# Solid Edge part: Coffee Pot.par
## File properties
Document Number: DOC NUMBER
Revision: REV NUMBER
Project Name: COFFEE MAKER
Title: COFFEE POT
Subject: COFFEE MAKER
Author: rkriggs
Keywords: POT
Comments: COMMENTS FIELD
Template: Normal.par
Last saved by: plm
Revision: 53
Application: Solid Edge
Category: COFFEE MAKER
Manager: MANAGER FIELD
Company: UGS
CUSTOM NAME FIELD: CUSTOM VALUE FIELD
Density: 0.09375032274 lbm/in^3
Accuracy: 0.99
圖檔名稱: Coffee Pot.par
圖檔編號: Coffee Pot.par
major_rev: A
classification: Mechanical/Part
generation: 2
id: 6B58A722315E453AA4D6A4DDAE715D26
authoring_tool: Solid Edge
thumbnail: vault:///?fileId=0F645047CE554D2D99C893C972FE50EA
Material: Glass, general industrial
Face Style: White (glass)
Fill Style: ANSI36(Marble)
Virtual Style: White (Glass)
Coef. of Thermal Exp: 0.0
Thermal Conductivity: 0.0
Specific Heat: 0.0
Modulus of Elasticity: 0.0
Poisson's Ratio: 0.0
Yield Stress: 0.0
Ultimate Stress: 0.0
Elongation: 0.0
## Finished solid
Body 1: solid body, 84 faces, 162 edges, 80 vertices.
  Faces by surface: blend 19, torus 18, spline 17, cylinder 12, plane 11, cone 7
  Edges by curve: circle 58, intersection 47, curve on surface 35, line 14, ellipse 8
Bounding box of the edges (mm; curved faces can reach further): 127.121 x 115.529 x 113.030, from (-57.7645, -57.7645, 0) to (69.356, 57.7645, 113.03).
Cylindrical faces by radius (mm): R1.9812 x4, R3.175 x1, R6.35 x1, R52.959 x1, R53.975 x2, R56.134 x1, R57.15 x2
Conical faces (half-angle, radius in mm at the cone's reference point): 9.0903 deg R52.9989 x1, 9.0903 deg R56.134 x1, 30 deg R41.7004 x1, 30 deg R44.45 x1, 32.6038 deg R54.4753 x1, 32.6038 deg R57.15 x1, 76.9156 deg R4.8324 x1
Toroidal faces (ring radius, tube radius in mm): R4.7337 r1.9812 x2, R40.7838 r3.175 x1, R40.7838 r6.35 x1, R49.9493 r3.175 x1, R49.9493 r6.35 x1, R50.8 r3.175 x2, R50.8 r6.35 x2, R53.975 r3.175 x1, R53.975 r6.35 x1, R55.5752 r1.9812 x2, R58.674 r1.524 x1, R59.309 r3.175 x1, R59.309 r6.35 x1, R60.325 r6.35 x1
Planar faces by outward normal: +z 3, -z 2, oblique 6
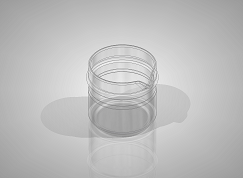
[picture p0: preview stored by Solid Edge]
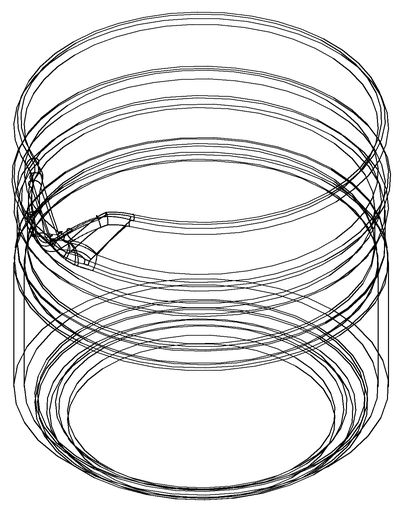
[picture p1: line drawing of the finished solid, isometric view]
